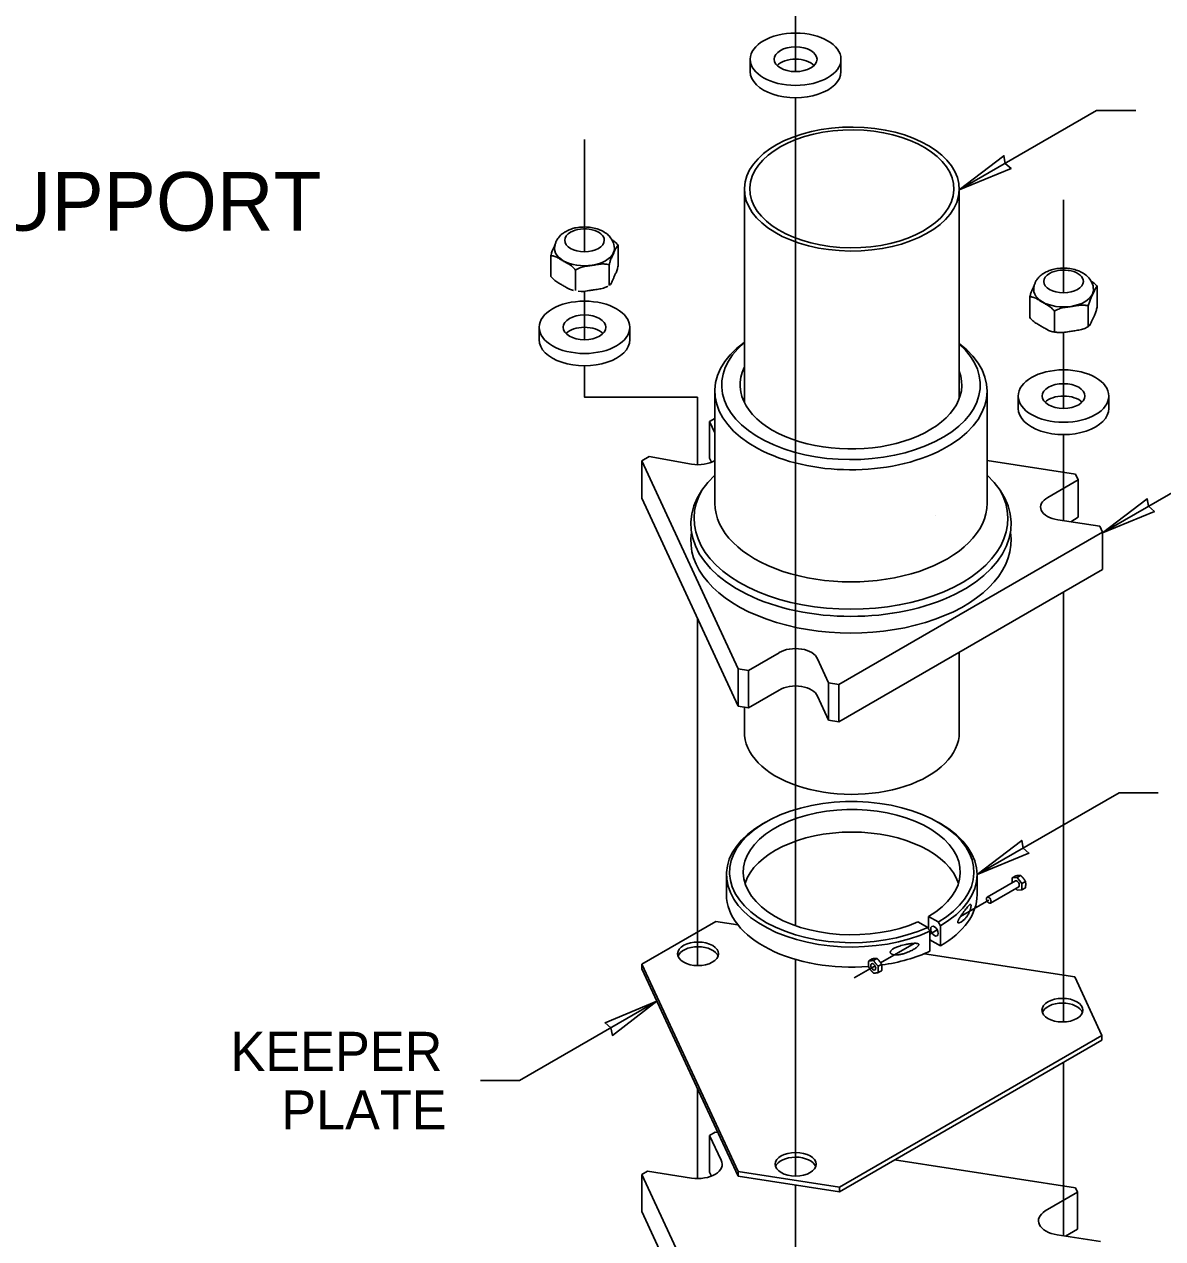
# Model space of a CAD drawing. Extents: x 99862 to 103151, y 100000 to 105076.
# Drawn here: x 101612.7 to 102079, y 100362.2 to 100859.6 of the extents above; entities that cross this region are included whole.
import ezdxf

# ---------------------------------------------------------------- set-up
doc = ezdxf.new("R2010")
doc.units = 0
for name, color, linetype in [('Level 1', 7, 'Continuous'), ('Level 12', 7, 'Continuous'), ('Level 15', 7, 'Continuous'), ('Level 16', 7, 'Continuous'), ('Level 2', 7, 'Continuous'), ('Level 20', 7, 'Continuous'), ('Level 4', 7, 'Continuous'), ('Level 5', 7, 'Continuous'), ('Level 6', 7, 'Continuous'), ('Level 7', 7, 'Continuous')]:
    doc.layers.add(name, color=color, linetype=linetype)

msp = doc.modelspace()

# ---------------------------------------------------------------- linework, layer by layer
at = {"layer": 'Level 1'}
for p, q in [((101985.76, 100658.37), (101985.76, 100658.37)), ((101916.27, 100532.76), (101915.37, 100532.24)), ((101987.96, 100532.24), (101987.06, 100532.76)), ((101900.33, 100511.29), (101900.33, 100503.07)), ((102002.99, 100503.07), (102002.99, 100511.29)), ((101983.09, 100494.19), (101983.09, 100489.11)), ((101983.09, 100494.19), (101987.06, 100491.9)), ((101982.76, 100489.68), (101978.76, 100491.99)), ((101987.96, 100490.33), (101987.06, 100491.9)), ((101987.96, 100482.11), (101987.96, 100490.33)), ((101983.66, 100479.9), (101983.66, 100488.12)), ((101983.66, 100484.59), (101987.96, 100482.11))]:
    msp.add_line(p, q, dxfattribs=at)
for centre, major_axis, start_param, end_param in [((101951.66, 100512.33), (50.05, 0), 5.497787, 11.665828), ((101951.66, 100512.33), (44.44, 0), 5.497787, 11.651205), ((101951.66, 100511.29), (51.33, 0), 2.356194, 5.385515), ((101951.66, 100511.29), (51.33, 0), 5.497787, 7.068583), ((101951.66, 100503.07), (44.44, 0), 0.181492, 2.9601), ((101951.66, 100503.07), (-51.33, 0), 6.283175, 7.989091), ((101951.66, 100503.07), (-51.33, 0), 2.356194, 3.141603), ((101951.66, 100503.07), (-51.33, 0), 1.811992, 2.243922)]:
    msp.add_ellipse(centre, major_axis=major_axis, ratio=0.57735, start_param=start_param, end_param=end_param, dxfattribs=at)
msp.add_ellipse((101985.52, 100488.15), major_axis=(1.09, -1.9), ratio=0.57735, dxfattribs=at)
for points, degree in [([(101998.59, 100497.48), (101998.84, 100497.8), (101999.07, 100498.1), (101999.51, 100498.61), (101999.73, 100498.83), (102000.02, 100499.05), (102000.11, 100499.11), (102000.28, 100499.14), (102000.36, 100499.13), (102000.45, 100498.99), (102000.47, 100498.93), (102000.5, 100498.75), (102000.51, 100498.64), (102000.5, 100498.38), (102000.48, 100498.23), (102000.44, 100497.93), (102000.41, 100497.78), (102000.31, 100497.34), (102000.23, 100497.07), (102000.05, 100496.55), (101999.96, 100496.31), (101999.66, 100495.62), (101999.45, 100495.21), (101999, 100494.47), (101998.77, 100494.13), (101998.28, 100493.51), (101998.03, 100493.23), (101997.51, 100492.71), (101997.24, 100492.48), (101996.69, 100492.07), (101996.41, 100491.89), (101995.98, 100491.68), (101995.83, 100491.62), (101995.55, 100491.54), (101995.41, 100491.52), (101995.21, 100491.56), (101995.15, 100491.58), (101995.06, 100491.7), (101995.04, 100491.81), (101995.07, 100492.08), (101995.12, 100492.23), (101995.23, 100492.51), (101995.29, 100492.64), (101995.5, 100493.03), (101995.64, 100493.26), (101995.92, 100493.72), (101996.06, 100493.94), (101996.49, 100494.58), (101996.77, 100494.98), (101997.32, 100495.76), (101997.58, 100496.12), (101998.1, 100496.83), (101998.35, 100497.17), (101998.59, 100497.48)], 3), ([(101982.76, 100489.68), (101983.06, 100489.16), (101983.36, 100488.64), (101983.66, 100488.12)], 2), ([(101972.45, 100482.39), (101973.55, 100482.67), (101974.63, 100482.88), (101976.19, 100483.08), (101976.71, 100483.14), (101977.46, 100483.17), (101977.7, 100483.18), (101978.18, 100483.16), (101978.42, 100483.13), (101978.74, 100483.04), (101978.84, 100483.01), (101979.01, 100482.88), (101979.09, 100482.8), (101979.1, 100482.56), (101979.04, 100482.41), (101978.88, 100482.16), (101978.78, 100482.05), (101978.47, 100481.73), (101978.24, 100481.54), (101977.76, 100481.18), (101977.52, 100481.02), (101976.78, 100480.56), (101976.28, 100480.29), (101975.25, 100479.79), (101974.72, 100479.56), (101973.12, 100478.96), (101972.04, 100478.66), (101970.39, 100478.44), (101969.84, 100478.41), (101969.04, 100478.46), (101968.78, 100478.5), (101968.27, 100478.62), (101968.03, 100478.71), (101967.73, 100478.92), (101967.64, 100479), (101967.5, 100479.2), (101967.46, 100479.31), (101967.43, 100479.55), (101967.45, 100479.68), (101967.55, 100479.93), (101967.63, 100480.05), (101967.9, 100480.39), (101968.13, 100480.59), (101968.63, 100480.93), (101968.89, 100481.08), (101969.69, 100481.49), (101970.24, 100481.71), (101971.35, 100482.09), (101971.9, 100482.25), (101972.45, 100482.39)], 3)]:
    msp.add_open_spline(points, degree=degree, dxfattribs=at)
at = {"layer": 'Level 12'}
for p, q in [((101910.06, 100845.26), (101910.06, 100840.21)), ((101947.21, 100845.26), (101947.21, 100840.21)), ((101855.97, 100760.61), (101855.97, 100769.03)), ((101828.35, 100764.76), (101828.35, 100756.34)), ((101838.46, 100758.92), (101838.46, 100750.5)), ((101852.27, 100761.06), (101852.27, 100752.63)), ((102024.59, 100747.9), (102024.59, 100739.48)), ((102052.22, 100743.75), (102052.22, 100752.18)), ((102048.52, 100744.2), (102048.52, 100735.78)), ((102034.71, 100742.07), (102034.71, 100733.64)), ((101823.59, 100735.46), (101823.59, 100730.41)), ((101860.74, 100735.46), (101860.74, 100730.41)), ((102019.83, 100707.32), (102019.83, 100702.26)), ((102056.98, 100707.32), (102056.98, 100702.26))]:
    msp.add_line(p, q, dxfattribs=at)
for centre, major_axis in [((101928.64, 100845.26), (-18.57, 0)), ((101928.64, 100845.26), (-8.77, 0)), ((101842.16, 100735.46), (-18.57, 0)), ((101842.16, 100735.46), (-8.77, 0)), ((102038.41, 100707.32), (-18.57, 0)), ((102038.41, 100707.32), (-8.77, 0))]:
    msp.add_ellipse(centre, major_axis=major_axis, ratio=0.57735, dxfattribs=at)
for centre, major_axis, start_param, end_param in [((101928.64, 100840.21), (-8.77, 0), 3.664192, 5.760586), ((101928.64, 100840.21), (-18.57, 0), 0, 3.141593), ((101842.16, 100771.11), (8.11, 0), 2.356194, 3.141593), ((101842.16, 100771.11), (8.11, 0), 6.283185, 8.63938), ((101842.16, 100767.74), (-12.23, 0), 0, 3.141593), ((101842.16, 100771.11), (8.11, 0), 3.141593, 6.283185), ((102038.41, 100754.25), (8.11, 0), 2.356194, 3.141593), ((102038.41, 100754.25), (8.11, 0), 6.283185, 8.63938), ((102038.41, 100754.25), (8.11, 0), 3.141593, 6.283185), ((102038.41, 100750.88), (-12.23, 0), 0, 3.141593), ((101842.16, 100730.41), (-8.77, 0), 3.664192, 5.760586), ((101842.16, 100730.41), (-18.57, 0), 0, 3.141593), ((102038.41, 100702.26), (-8.77, 0), 3.664192, 5.760586), ((102038.41, 100702.26), (-18.57, 0), 0, 3.141593)]:
    msp.add_ellipse(centre, major_axis=major_axis, ratio=0.57735, start_param=start_param, end_param=end_param, dxfattribs=at)
for points, degree in [([(101854.4, 100767.74), (101854.4, 100769.04), (101853.93, 100770.53), (101852.5, 100772.73), (101851.31, 100773.82), (101849.02, 100775.19), (101847.55, 100775.76), (101844.62, 100776.46), (101842.6, 100776.62), (101839.2, 100776.39), (101837.25, 100775.95), (101835.31, 100775.13), (101834.78, 100774.87), (101833.22, 100773.96), (101832.05, 100772.97), (101830.88, 100771.33), (101830.47, 100770.53), (101830.05, 100769.19), (101829.93, 100768.4), (101829.93, 100767.74)], 3), ([(101830.15, 100769.48), (101829.66, 100768.42), (101829.07, 100767.21), (101828.52, 100765.44), (101828.43, 100765.1), (101828.35, 100764.76)], 3), ([(101855.97, 100769.03), (101855.89, 100769.03), (101855.8, 100768.95), (101855.23, 100768.35), (101854.63, 100766.97), (101854.12, 100765.88), (101853.62, 100764.8), (101853.01, 100763.56), (101852.45, 100761.74), (101852.35, 100761.4), (101852.27, 100761.06)], 3), ([(101855.97, 100769.03), (101855.75, 100769.33), (101855.49, 100769.61), (101854.7, 100770.38), (101854.07, 100770.86), (101853.43, 100771.28)], 3), ([(101838.46, 100758.92), (101838.24, 100759.22), (101837.98, 100759.5), (101836.44, 100761), (101834.79, 100761.88), (101833.4, 100762.68), (101832.02, 100763.48), (101830.37, 100764.51), (101828.83, 100764.78), (101828.57, 100764.8), (101828.35, 100764.76)], 3), ([(101852.27, 100761.06), (101851.97, 100761.18), (101851.62, 100761.26), (101849.51, 100761.54), (101847.25, 100761.12), (101845.37, 100760.83), (101843.48, 100760.54), (101841.22, 100760.26), (101839.11, 100759.32), (101838.76, 100759.14), (101838.46, 100758.92)], 3), ([(101852.38, 100752.68), (101852.43, 100752.71), (101852.48, 100752.75), (101853.01, 100753.32), (101853.62, 100754.69), (101854.12, 100755.78), (101854.63, 100756.87), (101855.23, 100758.11), (101855.8, 100759.93), (101855.89, 100760.27), (101855.97, 100760.61)], 3), ([(102050.64, 100750.88), (102050.64, 100752.18), (102050.17, 100753.67), (102048.75, 100755.88), (102047.55, 100756.96), (102045.27, 100758.33), (102043.8, 100758.9), (102040.87, 100759.61), (102038.84, 100759.77), (102035.45, 100759.53), (102033.49, 100759.09), (102031.56, 100758.27), (102031.03, 100758.01), (102029.47, 100757.11), (102028.3, 100756.11), (102027.13, 100754.47), (102026.72, 100753.68), (102026.29, 100752.33), (102026.17, 100751.55), (102026.17, 100750.88)], 3), ([(101828.35, 100756.34), (101828.57, 100756.04), (101828.83, 100755.76), (101830.37, 100754.26), (101832.02, 100753.38), (101833.4, 100752.58), (101834.76, 100751.8), (101836.37, 100750.8), (101837.67, 100750.53)], 3), ([(102026.4, 100752.63), (102025.9, 100751.56), (102025.32, 100750.36), (102024.77, 100748.58), (102024.68, 100748.24), (102024.59, 100747.9)], 3), ([(102052.22, 100752.18), (102052, 100752.47), (102051.74, 100752.75), (102050.94, 100753.53), (102050.32, 100754), (102049.68, 100754.43)], 3), ([(101839.6, 100750.24), (101841.36, 100750.04), (101843.54, 100750.45), (101845.37, 100750.73), (101847.25, 100751.02), (101849.51, 100751.3), (101851.45, 100752.16), (101851.61, 100752.24), (101851.76, 100752.32)], 3), ([(102034.71, 100742.07), (102034.49, 100742.36), (102034.23, 100742.64), (102032.69, 100744.14), (102031.03, 100745.03), (102029.65, 100745.82), (102028.27, 100746.62), (102026.61, 100747.65), (102025.07, 100747.93), (102024.81, 100747.94), (102024.59, 100747.9)], 3), ([(102052.22, 100752.18), (102052.14, 100752.17), (102052.04, 100752.1), (102051.48, 100751.5), (102050.87, 100750.12), (102050.37, 100749.03), (102049.86, 100747.94), (102049.26, 100746.7), (102048.69, 100744.88), (102048.6, 100744.54), (102048.52, 100744.2)], 3), ([(102048.52, 100744.2), (102048.22, 100744.32), (102047.86, 100744.4), (102045.76, 100744.69), (102043.5, 100744.26), (102041.61, 100743.97), (102039.72, 100743.68), (102037.46, 100743.4), (102035.36, 100742.47), (102035.01, 100742.28), (102034.71, 100742.07)], 3), ([(102048.62, 100735.82), (102048.68, 100735.85), (102048.73, 100735.9), (102049.26, 100736.46), (102049.86, 100737.84), (102050.37, 100738.93), (102050.87, 100740.02), (102051.48, 100741.25), (102052.04, 100743.08), (102052.14, 100743.41), (102052.22, 100743.75)], 3), ([(102024.59, 100739.48), (102024.81, 100739.19), (102025.07, 100738.9), (102026.61, 100737.4), (102028.27, 100736.52), (102029.65, 100735.72), (102031, 100734.94), (102032.62, 100733.94), (102033.91, 100733.68)], 3), ([(102033.91, 100733.69), (102034.56, 100733.56), (102035.21, 100733.46), (102035.85, 100733.38)], 2), ([(102035.84, 100733.38), (102037.6, 100733.18), (102039.78, 100733.59), (102041.61, 100733.87), (102043.5, 100734.16), (102045.76, 100734.44), (102047.69, 100735.3), (102047.85, 100735.38), (102048.01, 100735.47)], 3), ([(102048, 100735.46), (102048.19, 100735.57), (102048.37, 100735.67), (102048.57, 100735.79), (102048.6, 100735.8), (102048.62, 100735.82)], 3)]:
    msp.add_open_spline(points, degree=degree, dxfattribs=at)
at = {"layer": 'Level 15'}
for p, q in [((101995.67, 100791.74), (102051.96, 100824.24)), ((102067.96, 100824.24), (102051.96, 100824.24)), ((102054.37, 100651.26), (102110.66, 100683.76)), ((102002.99, 100511.29), (102061.13, 100544.86)), ((102077.13, 100544.86), (102061.13, 100544.86)), ((101871.86, 100459.42), (101815.57, 100426.92)), ((101799.57, 100426.92), (101815.57, 100426.92))]:
    msp.add_line(p, q, dxfattribs=at)
for points in [[(101995.67, 100791.74), (102016.93, 100800.57), (102014.53, 100802.62), (102013.95, 100805.74)], [(102054.37, 100651.26), (102072.65, 100665.26), (102073.23, 100662.15), (102075.64, 100660.09)], [(102002.99, 100511.29), (102024.25, 100520.12), (102021.85, 100522.18), (102021.27, 100525.29)], [(101871.86, 100459.42), (101853.58, 100445.42), (101853, 100448.53), (101850.59, 100450.59)]]:
    msp.add_lwpolyline(points, close=True, dxfattribs=at)
at = {"layer": 'Level 16'}
for p, q in [((101928.64, 100840.2), (101928.64, 100871.36)), ((101928.64, 100490.38), (101928.64, 100829.49)), ((102038.41, 100749.57), (102038.41, 100787.63)), ((101842.16, 100730.4), (101842.16, 100750.27)), ((102038.41, 100702.25), (102038.41, 100733.42)), ((101888.47, 100706.92), (101888.47, 100679.18)), ((102038.41, 100656.31), (102038.41, 100691.54)), ((102038.41, 100450.96), (102038.41, 100627.1)), ((101888.47, 100616.28), (101888.47, 100474.04)), ((102007.78, 100500.84), (101996.22, 100494.17)), ((101986.68, 100488.66), (101983.66, 100486.92)), ((101977.15, 100483.16), (101963.44, 100475.24)), ((101928.64, 100387.86), (101928.64, 100476.58)), ((101961.19, 100473.94), (101952.6, 100468.98)), ((102038.41, 100363.42), (102038.41, 100434.43)), ((101888.47, 100423.62), (101888.47, 100386.82)), ((101928.64, 100266.04), (101928.64, 100384.18))]:
    msp.add_line(p, q, dxfattribs=at)
for points in [[(101842.16, 100812.36), (101842.16, 100766.43)], [(101842.16, 100719.69), (101842.16, 100706.92), (101888.47, 100706.92)]]:
    msp.add_lwpolyline(points, dxfattribs=at)
at = {"layer": 'Level 2'}
for p, q in [((102018.88, 100510.81), (102017.4, 100509.95)), ((102017.4, 100509.95), (102019.35, 100510.13)), ((102017.4, 100507.98), (102017.4, 100509.95)), ((102020.83, 100510.98), (102019.35, 100510.13)), ((102019.35, 100510.13), (102021.3, 100507.7)), ((102018.66, 100508.71), (102007.1, 100502.04)), ((102008.47, 100499.65), (102020.04, 100506.33)), ((102019.35, 100504.92), (102018.79, 100505.61)), ((102021.3, 100505.09), (102019.35, 100504.92)), ((102022.79, 100508.55), (102021.3, 100507.7)), ((102021.3, 100507.7), (102021.3, 100505.09)), ((102022.79, 100505.95), (102021.3, 100505.09)), ((101958.62, 100476.02), (101959.98, 100476.8)), ((101960.57, 100476.19), (101961.93, 100476.98)), ((101962.53, 100473.76), (101963.88, 100474.55)), ((101962.53, 100471.16), (101963.88, 100471.94))]:
    msp.add_line(p, q, dxfattribs=at)
for centre, major_axis, start_param, end_param in [((102019.35, 100507.52), (0.69, -1.19), 0, 3.141593), ((102020.94, 100508.44), (1.38, -2.39), 0.785398, 0.785399)]:
    msp.add_ellipse(centre, major_axis=major_axis, ratio=0.57735, start_param=start_param, end_param=end_param, dxfattribs=at)
for centre, major_axis in [((102007.78, 100500.84), (0.69, -1.19)), ((101960.47, 100473.53), (0.73, -1.26))]:
    msp.add_ellipse(centre, major_axis=major_axis, ratio=0.57735, dxfattribs=at)
for points in [[(102019.96, 100510.96), (102019.64, 100510.93), (102019.27, 100510.88), (102018.88, 100510.81)], [(102020.83, 100510.98), (102020.58, 100510.99), (102020.29, 100510.99), (102019.96, 100510.96)], [(102021.92, 100509.83), (102021.59, 100510.24), (102021.23, 100510.62), (102020.83, 100510.98)], [(102022.79, 100508.55), (102022.53, 100509), (102022.24, 100509.43), (102021.92, 100509.83)], [(102022.9, 100507.31), (102022.9, 100507.75), (102022.85, 100508.16), (102022.79, 100508.55)], [(102022.79, 100505.95), (102022.85, 100506.42), (102022.9, 100506.88), (102022.9, 100507.31)], [(101958.51, 100474.65), (101958.51, 100475.09), (101958.55, 100475.55), (101958.62, 100476.02)], [(101958.62, 100473.41), (101958.55, 100473.81), (101958.51, 100474.22), (101958.51, 100474.65)], [(101959.49, 100476.04), (101959.16, 100476.01), (101958.88, 100476.01), (101958.62, 100476.02)], [(101960.57, 100476.19), (101960.18, 100476.12), (101959.81, 100476.07), (101959.49, 100476.04)], [(101959.98, 100476.8), (101960.37, 100476.87), (101960.74, 100476.92), (101961.06, 100476.95)], [(101961.44, 100474.91), (101961.12, 100475.32), (101960.83, 100475.75), (101960.57, 100476.19)], [(101961.06, 100476.95), (101961.39, 100476.98), (101961.67, 100476.99), (101961.93, 100476.98)], [(101962.53, 100473.76), (101962.13, 100474.13), (101961.77, 100474.51), (101961.44, 100474.91)], [(101961.93, 100476.98), (101962.32, 100476.61), (101962.69, 100476.23), (101963.02, 100475.82)], [(101963.02, 100475.82), (101963.34, 100475.42), (101963.63, 100474.99), (101963.88, 100474.55)], [(101963.99, 100473.31), (101963.99, 100473.74), (101963.95, 100474.15), (101963.88, 100474.55)], [(101958.62, 100473.41), (101958.88, 100472.97), (101959.16, 100472.54), (101959.49, 100472.14)], [(101959.49, 100472.14), (101959.81, 100471.73), (101960.18, 100471.35), (101960.57, 100470.98)], [(101960.57, 100470.98), (101960.83, 100470.97), (101961.12, 100470.98), (101961.44, 100471.01)], [(101961.44, 100471.01), (101961.77, 100471.04), (101962.13, 100471.09), (101962.53, 100471.16)], [(101962.42, 100472.4), (101962.42, 100472.83), (101962.46, 100473.29), (101962.53, 100473.76)], [(101962.53, 100471.16), (101962.46, 100471.55), (101962.42, 100471.96), (101962.42, 100472.4)], [(101963.88, 100471.94), (101963.95, 100472.41), (101963.99, 100472.87), (101963.99, 100473.31)]]:
    msp.add_open_spline(points, degree=2, dxfattribs=at)
at = {"layer": 'Level 4'}
for p, q in [((101895.57, 100663.41), (101895.58, 100708.48)), ((102007.08, 100663.41), (102007.08, 100708.85))]:
    msp.add_line(p, q, dxfattribs=at)
for centre, major_axis, start_param, end_param in [((101951.32, 100709.31), (-55.76, 0), 5.613202, 10.075608), ((101951.32, 100711.85), (-52.97, 0), 5.682747, 10.002966), ((101951.32, 100711.85), (-45.42, 0), 6.008223, 9.64062), ((101951.32, 100654.94), (-65.6, 0), 5.728235, 9.979631), ((101951.32, 100657.11), (-64.29, 0), 5.953629, 9.754335), ((101951.32, 100663.4), (-55.76, 0), 6.282944, 9.424851), ((101951.32, 100648.1), (-65.6, 0), 6.192734, 9.515229)]:
    msp.add_ellipse(centre, major_axis=major_axis, ratio=0.57735, start_param=start_param, end_param=end_param, dxfattribs=at)
at = {"layer": 'Level 5'}
for p, q in [((101922.12, 100830.08), (101922.12, 100830.08)), ((101907.66, 100792.57), (101907.67, 100704.62)), ((101995.69, 100706.24), (101995.67, 100792.3)), ((101995.71, 100569.16), (101995.7, 100602.44)), ((101907.69, 100579.91), (101907.69, 100569.34))]:
    msp.add_line(p, q, dxfattribs=at)
for centre, major_axis, end_param in [((101951.66, 100792.1), (-44.01, 0), 12.552004), ((101951.68, 100792.18), (-41.81, 0), 12.552004), ((101951.7, 100569.57), (-44.01, 0), 9.426883)]:
    msp.add_ellipse(centre, major_axis=major_axis, ratio=0.57735, start_param=6.268969, end_param=end_param, dxfattribs=at)
at = {"layer": 'Level 6'}
for p, q in [((101893.44, 100696.87), (101895.58, 100698.11)), ((101893.44, 100681.81), (101893.44, 100696.87)), ((101895.58, 100692.27), (101893.44, 100696.87)), ((101865.63, 100680.82), (101868.67, 100682.57)), ((101865.63, 100680.82), (101865.63, 100665.51)), ((101905.18, 100595.6), (101865.63, 100680.82)), ((101868.67, 100682.57), (101886.05, 100679.35)), ((101894.19, 100680.2), (101893.44, 100681.81)), ((102007.08, 100680.98), (102043.35, 100675.37)), ((102043.35, 100675.37), (102044.46, 100672.97)), ((102044.46, 100672.97), (102032.03, 100665.79)), ((102044.46, 100672.97), (102044.46, 100657.67)), ((101905.18, 100580.3), (101865.63, 100665.51)), ((102036.1, 100656.67), (102053.26, 100654.01)), ((102044.46, 100657.67), (102041.33, 100655.86)), ((102053.26, 100654.01), (102054.37, 100651.62)), ((102054.37, 100651.62), (101946.32, 100589.23)), ((102054.37, 100651.62), (102054.37, 100636.31)), ((102054.37, 100636.31), (101946.32, 100573.93)), ((101921.89, 100602.21), (101909.33, 100594.96)), ((101942.16, 100589.88), (101937.61, 100599.68)), ((101909.33, 100594.96), (101905.18, 100595.6)), ((101905.18, 100595.6), (101905.18, 100580.3)), ((101909.33, 100594.96), (101909.33, 100579.65)), ((101946.32, 100589.23), (101942.16, 100589.88)), ((101942.16, 100589.88), (101942.16, 100574.57)), ((101946.32, 100589.23), (101946.32, 100573.93)), ((101921.89, 100586.91), (101909.33, 100579.65)), ((101942.16, 100574.57), (101937.61, 100584.38)), ((101909.33, 100579.65), (101905.18, 100580.3)), ((101946.32, 100573.93), (101942.16, 100574.57)), ((101893.44, 100404.51), (101895.75, 100405.85)), ((101893.44, 100389.45), (101893.44, 100404.51)), ((101898.19, 100394.29), (101893.44, 100404.51)), ((101895.75, 100405.85), (101896.8, 100405.69)), ((101969.22, 100394.48), (102043.34, 100383.02)), ((101865.63, 100388.45), (101867.94, 100389.79)), ((101867.94, 100389.79), (101886.05, 100386.99)), ((101865.63, 100373.39), (101865.63, 100388.45)), ((101905.17, 100303.24), (101865.63, 100388.45)), ((101894.19, 100387.84), (101893.44, 100389.45)), ((102044.19, 100381.19), (102030.93, 100373.54)), ((102043.34, 100383.02), (102044.19, 100381.19)), ((102044.19, 100366.13), (102044.19, 100381.19)), ((101905.17, 100288.18), (101865.63, 100373.39)), ((102044.19, 100366.13), (102039.26, 100363.29)), ((102035.81, 100363.82), (102053.52, 100361.08))]:
    msp.add_line(p, q, dxfattribs=at)
for centre, major_axis, start_param, end_param in [((101888.47, 100685.02), (-10.11, 0), 1.328774, 2.348909), ((102038.23, 100661.85), (9.22, 0), 2.307312, 4.479825), ((101928.6, 100598.56), (-9.22, 0), 3.354509, 5.527023), ((101928.6, 100583.25), (-9.22, 0), 3.354509, 5.527023), ((101888.47, 100392.66), (-10.11, 0), 1.328774, 3.424981), ((102038.22, 100369.49), (10.11, 0), 2.375971, 4.472179)]:
    msp.add_ellipse(centre, major_axis=major_axis, ratio=0.57735, start_param=start_param, end_param=end_param, dxfattribs=at)
at = {"layer": 'Level 7'}
for p, q in [((101865.72, 100474.6), (101895.92, 100492.04)), ((101895.94, 100492.15), (101904.98, 100490.75)), ((101865.72, 100472.65), (101865.72, 100474.6)), ((101905.09, 100389.76), (101865.72, 100474.6)), ((101981.43, 100478.92), (102043.01, 100469.4)), ((101905.09, 100387.82), (101865.72, 100472.65)), ((102043.01, 100469.4), (102054.13, 100445.45)), ((102054.13, 100445.45), (101946.56, 100383.35)), ((102054.13, 100443.51), (102054.13, 100445.45)), ((102054.13, 100443.51), (101946.56, 100381.4)), ((101905.09, 100387.82), (101905.09, 100389.76)), ((101946.56, 100383.35), (101905.09, 100389.76)), ((101946.56, 100381.4), (101905.09, 100387.82)), ((101946.56, 100381.4), (101946.56, 100383.35))]:
    msp.add_line(p, q, dxfattribs=at)
for centre, start_param, end_param in [((101888.68, 100478.87), 2.541266, 8.823332), ((101888.68, 100476.93), 3.344107, 6.080671), ((102037.94, 100453.84), 3.344107, 6.080671), ((101928.67, 100390.75), 4.721171, 6.080671), ((101928.67, 100390.75), 3.344107, 4.721171)]:
    msp.add_ellipse(centre, major_axis=(-8.37, 0), ratio=0.57735, start_param=start_param, end_param=end_param, dxfattribs=at)
for centre in [(102037.94, 100455.78), (101928.67, 100392.69)]:
    msp.add_ellipse(centre, major_axis=(-8.37, 0), ratio=0.57735, dxfattribs=at)

# ---------------------------------------------------------------- texts
at = {"layer": 'Level 20'}
for s, height, p in [('TYPE PL-T SIGN SUPPORT', 24, (101320.64, 100775.04)), ('KEEPER', 16, (101697.15, 100430.92)), ('PLATE', 16, (101717.93, 100406.92))]:
    msp.add_text(s, height=height, dxfattribs=at).set_placement(p)

doc.saveas('drawing.dxf')
